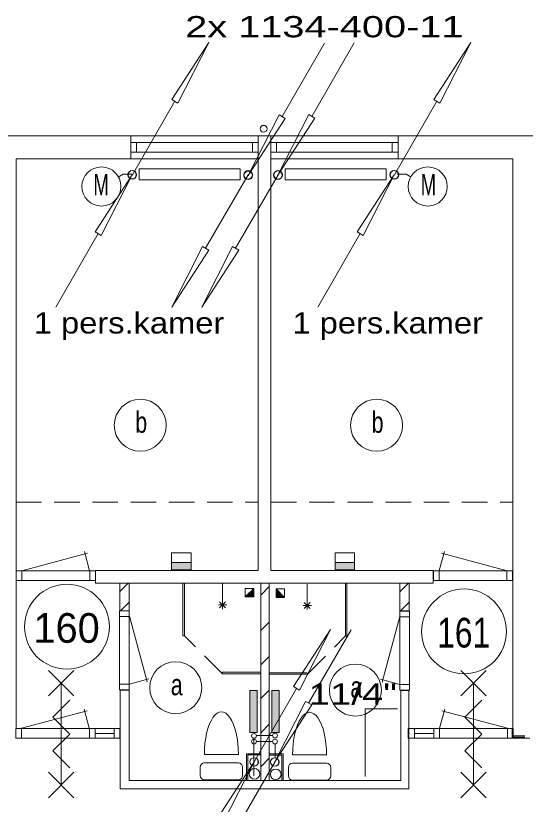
# Model space of a CAD drawing. Extents: x 295824 to 414724, y 24924 to 109024.
# Drawn here: x 320086 to 326087, y 71286 to 80577 of the extents above; entities that cross this region are included whole.
import ezdxf
from ezdxf.enums import TextEntityAlignment as Align

# ---------------------------------------------------------------- set-up
doc = ezdxf.new("R2010")
doc.units = 0
doc.header["$LTSCALE"] = 100
doc.linetypes.add('LONG_DASHED', pattern=[7.5, 6, -1.5])
doc.linetypes.add('MEDIUM_DASHED', pattern=[4.5, 3, -1.5])
doc.layers.add('16', color=7, linetype='Continuous', lineweight=13)
doc.layers.add('61', color=7, linetype='Continuous', lineweight=13)

msp = doc.modelspace()

# ---------------------------------------------------------------- hatches: boundary and pattern name
at = {"layer": '16'}
for points in [[(322152.7, 74047.1), (321921.2, 74047.1), (321921.2, 74133.6), (322152.7, 74133.6)], [(324077.6, 74047.1), (323846.1, 74047.1), (323846.1, 74133.6), (324077.6, 74133.6)], [(322843.9, 72625.1), (322929.4, 72625.1), (322929.4, 72132.9), (322843.9, 72132.9)], [(323103.1, 72625.1), (323188.5, 72625.1), (323188.5, 72132.9), (323103.1, 72132.9)]]:
    msp.add_hatch(color=256, dxfattribs=at).paths.add_polyline_path(points)
at = {"layer": '61'}
for points in [[(322789.4, 73728.2), (322889.4, 73828.2), (322889.4, 73728.2)], [(323251.9, 73722.8), (323151.9, 73822.8), (323151.9, 73722.8)]]:
    msp.add_hatch(color=256, dxfattribs=at).paths.add_polyline_path(points)

# ---------------------------------------------------------------- linework, layer by layer
at = {"layer": '16'}
for p, q in [((323723, 80255.2), (323223, 79389.2)), ((324072.1, 80257), (323572.1, 79391)), ((321459.4, 78704.2), (321959.4, 79570.2)), ((324546.2, 78704.2), (325046.2, 79570.2)), ((322822.5, 78703.1), (322322.5, 77837.1)), ((323175.9, 78703.1), (322675.9, 77837.1)), ((320555.8, 77144.1), (321055.8, 78010.1)), ((323642.5, 77144.1), (324142.5, 78010.1)), ((321921.2, 74133.6), (321921.2, 74247.5)), ((323846.1, 74133.6), (323846.1, 74247.5)), ((324035.7, 73342.8), (323535.7, 72476.8)), ((322892.7, 71784.4), (323392.7, 72650.4)), ((322891.2, 71619.1), (322891.2, 72058.7)), ((323111.5, 72094.1), (322919.8, 72094.1)), ((323137.1, 71783), (322637.1, 70917))]:
    msp.add_line(p, q, dxfattribs=at)
at = {"layer": '16', "linetype": 'LONG_DASHED'}
for p, q in [((322919.9, 72023.4), (323111.4, 72023.4)), ((323142.4, 71834), (323142.4, 71997.6))]:
    msp.add_line(p, q, dxfattribs=at)
at = {"layer": '16'}
for points in [[(322359.4, 80263.2), (321995.4, 79549.2), (321923.4, 79591.2)], [(325446.2, 80263.2), (325082.2, 79549.2), (325010.2, 79591.2)], [(322823, 78696.2), (323187, 79410.2), (323259, 79368.2)], [(323172.1, 78698), (323536.1, 79412), (323608.1, 79370)], [(321455.8, 78703.1), (321091.8, 77989.1), (321019.8, 78031.1)], [(321538.3, 78644.2), (322728.2, 78644.2), (322728.2, 78773.8), (321538.3, 78773.8)], [(323258.4, 78644.2), (324448.3, 78644.2), (324448.3, 78773.8), (323258.4, 78773.8)], [(324542.5, 78703.1), (324178.5, 77989.1), (324106.5, 78031.1)], [(321922.5, 77144.1), (322286.5, 77858.1), (322358.5, 77816.1)], [(322275.9, 77144.1), (322639.9, 77858.1), (322711.9, 77816.1)], [(322152.7, 74047.1), (321921.2, 74047.1), (321921.2, 74133.6), (322152.7, 74133.6)], [(324077.6, 74047.1), (323846.1, 74047.1), (323846.1, 74133.6), (324077.6, 74133.6)], [(323792.7, 73343.4), (323428.7, 72629.4), (323356.7, 72671.4)], [(322843.9, 72625.1), (322929.4, 72625.1), (322929.4, 72132.9), (322843.9, 72132.9)], [(323103.1, 72625.1), (323188.5, 72625.1), (323188.5, 72132.9), (323103.1, 72132.9)], [(323135.7, 71783.8), (323499.7, 72497.8), (323571.7, 72455.8)], [(322894.5, 71784), (322530.5, 71070), (322458.5, 71112)]]:
    msp.add_lwpolyline(points, close=True, dxfattribs=at)
for points in [[(321455.8, 78710.9), (321349.8, 78710.9), (321290.3, 78676.5)], [(324577.9, 78710.9), (324683.9, 78710.9), (324743.4, 78676.5)], [(322152.7, 74133.6), (322152.7, 74247.5), (321921.2, 74247.5)], [(324077.6, 74133.6), (324077.6, 74247.5), (323846.1, 74247.5)], [(324201.4, 71612.7), (324201.4, 72409), (324584, 72409)]]:
    msp.add_lwpolyline(points, dxfattribs=at)
for centre, radius in [((321094.7, 78565.5), 229.9), ((324939, 78565.5), 229.9), ((321455.8, 78702.8), 50), ((321459.4, 78703.9), 50), ((322822.5, 78703.4), 50), ((322823, 78696.5), 50), ((323172.1, 78698.3), 50), ((323175.9, 78703.4), 50), ((324542.5, 78702.8), 50), ((324546.2, 78703.9), 50), ((322892, 72091.2), 27.9), ((323139.4, 72094.1), 27.9), ((322892, 72023.4), 27.9), ((323139.4, 72023.4), 27.9), ((322892.7, 71784.1), 50), ((322894.5, 71783.7), 50), ((323135.7, 71784.1), 50), ((323137.1, 71783.3), 50)]:
    msp.add_circle(centre, radius, dxfattribs=at)
at = {"layer": '61'}
for p, q in [((321440.7, 78890.8), (321440.7, 79160.8)), ((321507.4, 78969), (321507.4, 79082.9)), ((322872.5, 78968.4), (322872.5, 79082.4)), ((322940.1, 79160.6), (322940.1, 74040.8)), ((323090.1, 79153), (323090.1, 74040.8)), ((323156, 78969.4), (323156, 79083.4)), ((324520.3, 78969.1), (324520.3, 79082.7)), ((324588.7, 78890.8), (324588.7, 79160.9)), ((320090.1, 78890.8), (322940.1, 78890.8)), ((320090.1, 72179.8), (320090.1, 78890.8)), ((325940.1, 78890.8), (323090.1, 78890.8)), ((325940.1, 72065.8), (325940.1, 78890.8)), ((320156.3, 74036.8), (320929, 74243.8)), ((320954.7, 74037.4), (320893.9, 74264.3)), ((325074.1, 74038.5), (325134.9, 74265.4)), ((325872.5, 74037.9), (325099.8, 74244.9)), ((320157, 73922.2), (320157, 74036.2)), ((320957, 73922.2), (320957, 74036.2)), ((321024, 73922.2), (321024, 74036.2)), ((325004.7, 73923.2), (325004.7, 74037.2)), ((325071.7, 73923.2), (325071.7, 74037.2)), ((325871.7, 73923.2), (325871.7, 74037.2)), ((321309.2, 73789.9), (321408.9, 73889.6)), ((321310.7, 73566.1), (321310.7, 73890.2)), ((321310.7, 73890.2), (321420.7, 73890.2)), ((321420.7, 73566.1), (321420.7, 73890.2)), ((322071.9, 73890.5), (322071.9, 73270)), ((322521.8, 73684), (322521.8, 73884)), ((322973.8, 73890.8), (322973.8, 71565.8)), ((323070.1, 73890.8), (323070.1, 71565.8)), ((323519.5, 73678.6), (323519.5, 73878.6)), ((323969.4, 73885.1), (323969.4, 73264.6)), ((324609.7, 73566.1), (324609.7, 73890.2)), ((324609.7, 73890.2), (324719.6, 73890.2)), ((324611.4, 73789.9), (324711.1, 73889.6)), ((324719.6, 73566.1), (324719.6, 73890.2)), ((322974.4, 73754.6), (323070.1, 73850.4)), ((322521.8, 73684), (322521.8, 73584)), ((321321.5, 73567.3), (321421.2, 73667)), ((322571.8, 73634), (322471.8, 73634)), ((322557.2, 73669.3), (322486.4, 73598.6)), ((322557.2, 73598.6), (322486.4, 73669.3)), ((323469.5, 73628.6), (323569.5, 73628.6)), ((323484.1, 73664), (323554.9, 73593.3)), ((323484.1, 73593.3), (323554.9, 73664)), ((323519.5, 73678.6), (323519.5, 73578.6)), ((324620, 73567.3), (324719.7, 73667)), ((321308.9, 73565.2), (321308.9, 72632.8)), ((321308.9, 73499.8), (321422.9, 73499.8)), ((321310.7, 73566.1), (321420.7, 73566.1)), ((321426.1, 73500.6), (321633.1, 72727.8)), ((324609, 73562.6), (324723, 73562.6)), ((324609.7, 73566.1), (324719.6, 73566.1)), ((324722.4, 73562.6), (324722.4, 72628.6)), ((322974.4, 73336.5), (323070.1, 73432.3)), ((324610.3, 73496.3), (324403.2, 72723.6)), ((324722.4, 73495.6), (324608.4, 73495.6)), ((322974.4, 72931.9), (323070.1, 73027.7)), ((320770.9, 72863), (320470.9, 72563)), ((320470.9, 72863), (320770.9, 72563)), ((325626.8, 72863), (325326.8, 72563)), ((325326.8, 72863), (325626.8, 72563)), ((321426.7, 72702.2), (321653.6, 72762.9)), ((322972, 72840.5), (322522.8, 72840.5)), ((322522.8, 72822.5), (322522.8, 72840.5)), ((322972.3, 72822.5), (322522.8, 72822.5)), ((323069, 72817.1), (323518.5, 72817.1)), ((323069.3, 72835.1), (323518.5, 72835.1)), ((323518.5, 72817.1), (323518.5, 72835.1)), ((324609.7, 72697.9), (324382.8, 72758.7)), ((320620.9, 71513), (320620.9, 72713)), ((321308.9, 72699.8), (321422.9, 72699.8)), ((324722.4, 72695.6), (324608.4, 72695.6)), ((325476.8, 71513), (325476.8, 72713)), ((321314.9, 72629.2), (321314.9, 72063.4)), ((321314.9, 72629.2), (321420.1, 72629.2)), ((322974.4, 72535.9), (323070.1, 72631.7)), ((324620.1, 72627.8), (324620.1, 71565.8)), ((324620.1, 72627.8), (324714.9, 72627.8)), ((324714.9, 72627.8), (324714.9, 72165.8)), ((320152.9, 72180.4), (320925.7, 72387.5)), ((320951.3, 72181), (320890.5, 72407.9)), ((325078.7, 72181.1), (325139.4, 72407.9)), ((325877.1, 72180.4), (325104.3, 72387.5)), ((322974.4, 72132.6), (323070.1, 72228.3)), ((320153.7, 72065.8), (320153.7, 72179.8)), ((320953.7, 72065.8), (320953.7, 72179.8)), ((321020.7, 72065.8), (321020.7, 72179.8)), ((321246.7, 72119.9), (321020.7, 72119.9)), ((321246.7, 72065.8), (321246.7, 72179.8)), ((324783.3, 72065.8), (324783.3, 72179.8)), ((324783.3, 72119.9), (325009.3, 72119.9)), ((325009.3, 72065.8), (325009.3, 72179.8)), ((325076.3, 72065.8), (325076.3, 72179.8)), ((325876.3, 72065.8), (325876.3, 72179.8)), ((325931.5, 72065.8), (326141.5, 72065.8)), ((325942.4, 72092.1), (326083.6, 72092.1)), ((325942.4, 72077.1), (326083.6, 72077.1)), ((322707.5, 71873.6), (322307.5, 71873.6)), ((322820, 71866.2), (322970, 71866.2)), ((322820, 71566.2), (322820, 71866.2)), ((322974.4, 71731.7), (323070.1, 71827.4)), ((323070.1, 71865.8), (323220.1, 71865.8)), ((323220.1, 71865.8), (323220.1, 71565.8)), ((323746.9, 71868.7), (323346.9, 71868.7)), ((322307.5, 71773.6), (322707.5, 71773.6)), ((323346.9, 71768.7), (323746.9, 71768.7)), ((320770.9, 71663), (320470.9, 71363)), ((320470.9, 71663), (320770.9, 71363)), ((322257.5, 71623.6), (322257.5, 71723.6)), ((322757.5, 71723.6), (322757.5, 71623.6)), ((323296.9, 71618.7), (323296.9, 71718.7)), ((323796.9, 71718.7), (323796.9, 71618.7)), ((325626.8, 71663), (325326.8, 71363)), ((325326.8, 71663), (325626.8, 71363)), ((322707.5, 71573.6), (322307.5, 71573.6)), ((323746.9, 71568.7), (323346.9, 71568.7))]:
    msp.add_line(p, q, dxfattribs=at)
at = {"layer": '61', "linetype": 'MEDIUM_DASHED'}
for p, q in [((320089.5, 74844.1), (322938.6, 74844.1)), ((323091.9, 74844.1), (325938.9, 74844.1)), ((322520.8, 72822.9), (322073.9, 73269.8)), ((323520.5, 72817.6), (323967.4, 73264.5))]:
    msp.add_line(p, q, dxfattribs=at)
at = {"layer": '61'}
for points in [[(301796.6, 66927.7), (301820.1, 79160.8), (332210.1, 79160.8)], [(320090, 73922.2), (320090, 74036.2), (321024, 74036.2)], [(321024, 73922.2), (320090, 73922.2), (320090, 74036.2)], [(322939.9, 74040.8), (321024.9, 74040.8), (321024.9, 73890.8), (325004.2, 73890.8)], [(323089.9, 74040.8), (325004.2, 74040.8), (325004.2, 73890.8)], [(325938.7, 73923.2), (325938.7, 74037.2), (325004.7, 74037.2)], [(325004.7, 73923.2), (325938.7, 73923.2), (325938.7, 74037.2)], [(322053.9, 73890.5), (322053.9, 73270), (322071.9, 73270)], [(323987.4, 73885.1), (323987.4, 73264.6), (323969.4, 73264.6)], [(322889.4, 73828.2), (322889.4, 73728.2), (322789.4, 73728.2)], [(323151.9, 73822.8), (323151.9, 73722.8), (323251.9, 73722.8)], [(321420.1, 72629.2), (321420.1, 71565.8), (324620.1, 71565.8)], [(320720.9, 71713), (320520.9, 71913), (320720.9, 72113), (320520.9, 72313), (320720.9, 72513)], [(325576.8, 71713), (325376.8, 71913), (325576.8, 72113), (325376.8, 72313), (325576.8, 72513)], [(321314.9, 72065.8), (321314.9, 71465.8), (324714.9, 71465.8), (324714.9, 72065.8)], [(322805, 71566.2), (322805, 71881.2), (322970, 71881.2)], [(323070.1, 71880.8), (323235.1, 71880.8), (323235.1, 71565.8)]]:
    msp.add_lwpolyline(points, dxfattribs=at)
for points in [[(321440.6, 78968.9), (321440.6, 79082.9), (322939.3, 79082.9), (322939.3, 78968.9)], [(323089.6, 78969.1), (323089.6, 79083.1), (324589, 79083.1), (324589, 78969.1)], [(322889.4, 73828.2), (322789.4, 73828.2), (322789.4, 73728.2)], [(322789.4, 73728.2), (322889.4, 73828.2), (322889.4, 73728.2)], [(323151.9, 73822.8), (323251.9, 73822.8), (323251.9, 73722.8)], [(323251.9, 73722.8), (323151.9, 73822.8), (323151.9, 73722.8)], [(321308.9, 72631.9), (321422.9, 72631.9), (321422.9, 73565.9), (321308.9, 73565.9)], [(324722.4, 73562.6), (324722.4, 72628.6), (324608.4, 72628.6), (324608.4, 73562.6)], [(320086.7, 72065.8), (320086.7, 72179.8), (321313, 72179.8), (321313, 72065.8)], [(320086.7, 72065.8), (320086.7, 72179.8), (321313, 72179.8), (321313, 72065.8)], [(324708, 72065.8), (324708, 72179.8), (325935, 72179.8), (325935, 72065.8)], [(324716.3, 72065.8), (324716.3, 72179.8), (325943.3, 72179.8), (325943.3, 72065.8)]]:
    msp.add_lwpolyline(points, close=True, dxfattribs=at)
for centre, radius in [((323005.3, 79245.8), 40), ((321552.2, 75751.7), 306.3), ((324336.3, 75751.7), 306.3), ((320688.9, 73377.9), 500), ((325366.2, 73322.2), 500), ((321969.8, 72659), 306.3), ((324085.7, 72631.2), 306.3), ((322897.6, 71643.7), 62.5), ((323147.6, 71638.2), 62.5)]:
    msp.add_circle(centre, radius, dxfattribs=at)
for centre, start, end in [((322307.5, 71723.6), 90, 180), ((322707.5, 71723.6), 0, 90), ((323346.9, 71718.7), 90, 180), ((323746.9, 71718.7), 0, 90), ((322307.5, 71623.6), 180, 270), ((322707.5, 71623.6), 270, 0), ((323346.9, 71618.7), 180, 270), ((323746.9, 71618.7), 270, 0)]:
    msp.add_arc(centre, 50, start, end, dxfattribs=at)
for centre in [(322507.5, 71873.6), (323546.9, 71868.7)]:
    msp.add_ellipse(centre, major_axis=(0, 500), ratio=0.4, start_param=4.712389, end_param=7.853982, dxfattribs=at)

# ---------------------------------------------------------------- texts
at = {"layer": '16'}
for s, width, p in [('2x 1134-400-11', 1.4, (322081.4, 80323.7)), ('M', 0.65, (321000.7, 78462.5)), ('M', 0.65, (324855.9, 78462.5)), (' 11/4"', 1.35, (323410.9, 72459.2))]:
    msp.add_text(s, height=250, dxfattribs=dict(at, width=width)).set_placement(p)
at = {"layer": '61'}
for s, width, p in [('1 pers.kamer', 1.15, (320298.2, 76832.7)), ('1 pers.kamer', 1.15, (323345, 76832.7)), ('b', 0.75, (321494.2, 75662.5)), ('b', 0.75, (324278.3, 75662.5)), ('a', 0.75, (321911.8, 72569.9)), ('a', 0.75, (324027.7, 72542))]:
    msp.add_text(s, height=250, dxfattribs=dict(at, width=width)).set_placement(p)
msp.add_text('160', height=350, dxfattribs=at).set_placement((320684.6, 73188.1), align=Align.CENTER)
at = {"layer": '61', "width": 0.8}
msp.add_text('161', height=350, dxfattribs=at).set_placement((325361.9, 73132.3), align=Align.CENTER)

doc.saveas('drawing.dxf')
